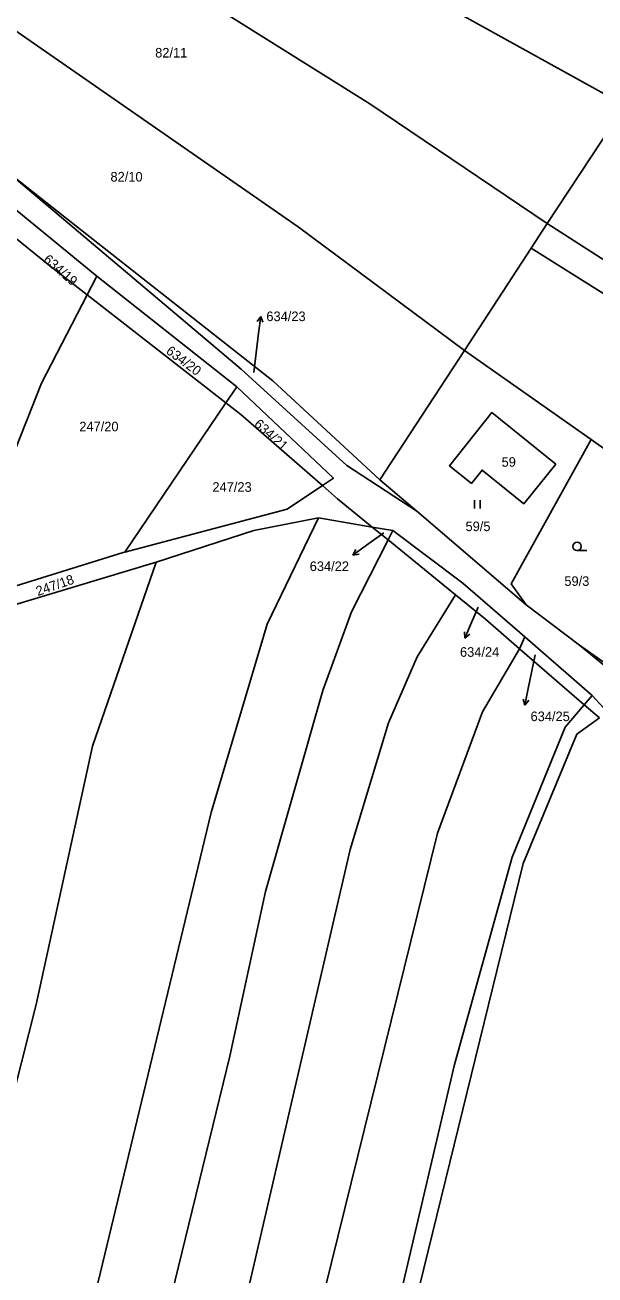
# Model space of a CAD drawing. Extents: x -746176 to -739709, y -1128407 to -1124482.
# Drawn here: x -743188.7 to -743087.7, y -1127796.2 to -1127574.6 of the extents above; entities that cross this region are included whole.
import ezdxf

# ---------------------------------------------------------------- set-up
doc = ezdxf.new("R2010")
doc.units = 0
for name, color, linetype in [('Vrstva 33', 7, 'Continuous'), ('Vrstva 42', 7, 'Continuous'), ('Vrstva 43', 7, 'Continuous'), ('Vrstva 44', 7, 'Continuous'), ('Vrstva 47', 7, 'Continuous')]:
    doc.layers.add(name, color=color, linetype=linetype)

msp = doc.modelspace()

# ---------------------------------------------------------------- linework, layer by layer
at = {"layer": 'Vrstva 33'}
for p, q in [((-743082.43, -1127588.87), (-743239.89, -1127501.37)), ((-743096.19, -1127609.82), (-743082.43, -1127588.87)), ((-743099.02, -1127614.17), (-743096.19, -1127609.82)), ((-743096.19, -1127609.82), (-743054.68, -1127636.42)), ((-743110.84, -1127632.34), (-743099.02, -1127614.17)), ((-743057.24, -1127640.46), (-743099.02, -1127614.17)), ((-743177.68, -1127622.43), (-743175.98, -1127619.13)), ((-743175.98, -1127619.13), (-743151.19, -1127638.77)), ((-743153.1, -1127641.6), (-743177.68, -1127622.43)), ((-743125.82, -1127655.26), (-743110.84, -1127632.34)), ((-743110.84, -1127632.34), (-743088.43, -1127648.09)), ((-743153.1, -1127641.6), (-743151.19, -1127638.77)), ((-743170.99, -1127668.05), (-743153.1, -1127641.6)), ((-743062.98, -1127666.21), (-743088.43, -1127648.09)), ((-743119.31, -1127660.83), (-743125.82, -1127655.26)), ((-743136.68, -1127662.01), (-743127.19, -1127663.61)), ((-743099.92, -1127677.43), (-743119.31, -1127660.83)), ((-743124.37, -1127665.91), (-743127.19, -1127663.61)), ((-743127.19, -1127663.61), (-743123.51, -1127664.23)), ((-743124.37, -1127665.91), (-743123.51, -1127664.23)), ((-743112.44, -1127675.65), (-743124.37, -1127665.91)), ((-743165.44, -1127669.87), (-743196.8, -1127679.29)), ((-743099.92, -1127677.43), (-743090.48, -1127684.56)), ((-743101.11, -1127685.19), (-743100.14, -1127683.11)), ((-743100.14, -1127683.11), (-743088.2, -1127693.47)), ((-743089.62, -1127695.12), (-743101.11, -1127685.19)), ((-743089.62, -1127695.12), (-743088.2, -1127693.47)), ((-743088.2, -1127693.47), (-743085.48, -1127696.45)), ((-743086.91, -1127697.47), (-743089.62, -1127695.12))]:
    msp.add_line(p, q, dxfattribs=at)
for points in [[(-743096.19, -1127609.82), (-743127.6, -1127588.59), (-743246.36, -1127514.17)], [(-743110.84, -1127632.34), (-743140.32, -1127610.37), (-743254.82, -1127530.84)], [(-743201.77, -1127597.55), (-743195.41, -1127603.21), (-743175.98, -1127619.13)], [(-743119.31, -1127660.83), (-743131.7, -1127652.73), (-743150.41, -1127635.6), (-743191.76, -1127600.69)], [(-743191.76, -1127600.69), (-743179.42, -1127610.43), (-743144.82, -1127637.7), (-743125.82, -1127655.26)], [(-743177.68, -1127622.43), (-743184.29, -1127617.28), (-743197.68, -1127606.48)], [(-743200.21, -1127677.12), (-743191.34, -1127652.2), (-743185.76, -1127638.12), (-743177.68, -1127622.43)], [(-743151.19, -1127638.77), (-743134.07, -1127654.97), (-743136.01, -1127656.26)], [(-743136.01, -1127656.26), (-743150.46, -1127643.66), (-743153.1, -1127641.6)], [(-743094.66, -1127652.45), (-743100.33, -1127659.49), (-743107.72, -1127653.53), (-743109.62, -1127655.89), (-743113.52, -1127652.75), (-743105.97, -1127643.33), (-743094.66, -1127652.45)], [(-743088.43, -1127648.09), (-743102.6, -1127673.7), (-743099.92, -1127677.43)], [(-743136.01, -1127656.26), (-743142.28, -1127660.44), (-743170.99, -1127668.05)], [(-743136.01, -1127656.26), (-743133.32, -1127658.6), (-743127.19, -1127663.61)], [(-743136.68, -1127662.01), (-743145.81, -1127680.82), (-743155.72, -1127714.23), (-743186.13, -1127840.64), (-743218.63, -1127971.66), (-743232.97, -1128020.31)], [(-743165.44, -1127669.87), (-743148.15, -1127664.23), (-743136.68, -1127662.01)], [(-743123.51, -1127664.23), (-743111.14, -1127673.56), (-743100.14, -1127683.11)], [(-743211.94, -1127995.24), (-743177.21, -1127859.16), (-743152.4, -1127757.44), (-743146.1, -1127728.25), (-743135.93, -1127692.62), (-743130.84, -1127678.65), (-743124.37, -1127665.91)], [(-743170.99, -1127668.05), (-743171.32, -1127668.14), (-743200.21, -1127677.12)], [(-743237.87, -1127943.87), (-743228.87, -1127911.59), (-743204.89, -1127820), (-743186.75, -1127748.28), (-743176.72, -1127702.48), (-743165.44, -1127669.87)], [(-743183.31, -1127943.86), (-743166.85, -1127875.07), (-743131.1, -1127720.81), (-743124.32, -1127698.36), (-743119.23, -1127686.62), (-743112.44, -1127675.65)], [(-743101.11, -1127685.19), (-743107.14, -1127679.98), (-743112.44, -1127675.65)], [(-743090.48, -1127684.56), (-743071.53, -1127700.11), (-743061.74, -1127702.4), (-743058.22, -1127699.76)], [(-743159.84, -1127901.41), (-743140.31, -1127817.95), (-743115.61, -1127717.91), (-743107.65, -1127696.37), (-743101.11, -1127685.19)], [(-743089.62, -1127695.12), (-743093.02, -1127699.07), (-743102.39, -1127722.13), (-743112.61, -1127758.91), (-743139.42, -1127873.34), (-743159.84, -1127901.41)], [(-743086.91, -1127697.47), (-743090.95, -1127700.36), (-743100.45, -1127723.29), (-743120.32, -1127804.45), (-743137.57, -1127875.6)]]:
    msp.add_lwpolyline(points, dxfattribs=at)
at = {"layer": 'Vrstva 43'}
for p, q in [((-743146.94, -1127626.26), (-743147.56, -1127627.19)), ((-743147.31, -1127629.24), (-743146.94, -1127626.26)), ((-743146.94, -1127626.26), (-743146.57, -1127627.32)), ((-743148.16, -1127636.21), (-743147.31, -1127629.24)), ((-743125.15, -1127664.66), (-743128.21, -1127666.85)), ((-743128.21, -1127666.85), (-743130.64, -1127668.61)), ((-743130.64, -1127668.61), (-743130.12, -1127667.62)), ((-743130.64, -1127668.61), (-743129.53, -1127668.43)), ((-743108.42, -1127677.83), (-743109.59, -1127680.57)), ((-743110.76, -1127683.33), (-743110.83, -1127682.22)), ((-743109.59, -1127680.57), (-743110.76, -1127683.33)), ((-743110.76, -1127683.33), (-743109.91, -1127682.61)), ((-743098.31, -1127686.3), (-743099.54, -1127692.26)), ((-743099.54, -1127692.26), (-743100.16, -1127695.2)), ((-743100.16, -1127695.2), (-743100.45, -1127694.11)), ((-743100.16, -1127695.2), (-743099.47, -1127694.32))]:
    msp.add_line(p, q, dxfattribs=at)
at = {"layer": 'Vrstva 44'}
for p, q in [((-743109.08, -1127660.33), (-743109.08, -1127658.83)), ((-743108.08, -1127660.33), (-743108.08, -1127658.83)), ((-743090.9, -1127667.8), (-743089.15, -1127667.8))]:
    msp.add_line(p, q, dxfattribs=at)
msp.add_circle((-743090.9, -1127667.05), 0.75, dxfattribs=at)
at = {"layer": 'Vrstva 47'}
msp.add_line((-743090.48, -1127684.56), (-743072.72, -1127697.13), dxfattribs=at)

# ---------------------------------------------------------------- texts
at = {"layer": 'Vrstva 42'}
for s, p in [('82/11', (-743165.64, -1127580.37)), ('82/10', (-743173.56, -1127602.36)), ('634/23', (-743145.94, -1127627.11)), ('247/20', (-743179.08, -1127646.64)), ('59', (-743104.27, -1127652.93)), ('247/23', (-743155.5, -1127657.37)), ('59/5', (-743110.66, -1127664.34)), ('634/22', (-743138.26, -1127671.42)), ('59/3', (-743093.15, -1127674.05)), ('634/24', (-743111.64, -1127686.62)), ('634/25', (-743099.14, -1127698.03))]:
    msp.add_text(s, height=1.7, dxfattribs=at).set_placement(p)
for s, rotation, p in [('634/19', 319, (-743185.57, -1127616.4)), ('634/20', 323, (-743163.86, -1127632.7)), ('634/21', 318, (-743148.25, -1127645.56)), ('247/18', 19, (-743186.43, -1127675.86))]:
    msp.add_text(s, height=1.7, rotation=rotation, dxfattribs=at).set_placement(p)

doc.saveas('drawing.dxf')
